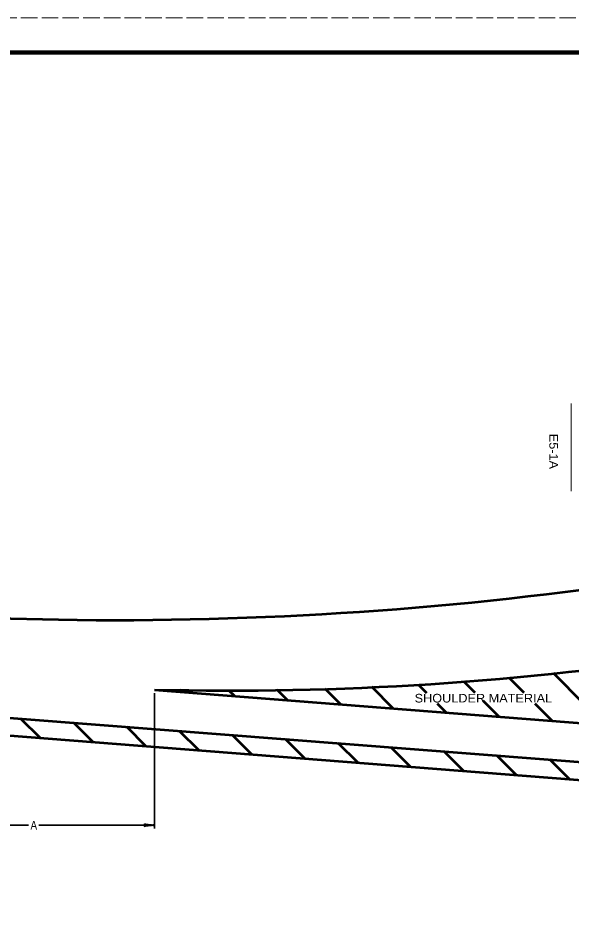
# Model space of a CAD drawing. Extents: x -281 to 399, y -258 to 182.
# Drawn here: x 24.5 to 184.7, y -78.8 to 181.6 of the extents above; entities that cross this region are included whole.
import ezdxf
from ezdxf.enums import TextEntityAlignment as Align

# ---------------------------------------------------------------- set-up
doc = ezdxf.new("R2010")
doc.units = 0
doc.header["$LTSCALE"] = 0.8
doc.linetypes.add('LONG_DASHED', pattern=[7.5, 6, -1.5])
doc.layers.add('1', color=7, linetype='Continuous', lineweight=53)
doc.layers.add('61', color=7, linetype='Continuous', lineweight=35)
doc.layers.add('2', color=7, linetype='Continuous')

msp = doc.modelspace()

# ---------------------------------------------------------------- linework, layer by layer
at = {"layer": '1', "lineweight": 13}
msp.add_line((184.743, 44.5429), (184.743, 69.8762), dxfattribs=at)
at = {"layer": '1'}
for p, q in [((-240.6297, 13.7625), (36.2368, 7.2891)), ((171.1573, -13.9157), (166.7939, -9.5523)), ((188.5777, -17.1941), (179.6273, -8.2436)), ((64.0117, -12.9926), (380.3567, -37.8742)), ((117.9044, -17.2314), (113.4621, -12.7891)), ((133.2538, -18.4387), (127.0237, -12.2087)), ((142.9353, -13.9781), (140.5067, -11.5495)), ((157.0136, -13.9142), (153.6852, -10.5857)), ((71.8562, -13.6096), (71.3122, -13.0657)), ((87.2056, -14.8168), (85.5973, -13.2087)), ((102.555, -16.0242), (99.584, -13.0532)), ((148.6033, -19.646), (146.0793, -17.1221)), ((163.9527, -20.8533), (159.3061, -16.2067)), ((179.3022, -22.0606), (174.3667, -17.1251)), ((30.984, -27.0359), (25.3669, -21.4188)), ((46.3254, -28.2353), (40.6921, -22.6018)), ((61.6668, -29.4345), (56.0172, -23.7848)), ((77.0083, -30.6338), (71.3423, -24.9679)), ((92.3498, -31.8332), (86.6675, -26.1509)), ((107.6912, -33.0325), (101.9927, -27.3339)), ((123.0327, -34.2317), (117.3178, -28.5169)), ((138.3741, -35.4311), (132.643, -29.6999)), ((153.7156, -36.6304), (147.9681, -30.883)), ((169.057, -37.8297), (163.2933, -32.066)), ((184.3984, -39.029), (178.6184, -33.249))]:
    msp.add_line(p, q, dxfattribs=at)
at = {"layer": '1', "lineweight": 35}
for p, q in [((64.0117, -13.9926), (64.0117, -53.25)), ((-5.8499, -52.25), (27.5809, -52.25)), ((30.5809, -52.25), (64.0117, -52.25))]:
    msp.add_line(p, q, dxfattribs=at)
at = {"layer": '1'}
for points in [[(-241.1311, -9.5059), (-85.5166, -12.8592), (381.7234, -48.9276)], [(383.4217, -54.5876), (-6.4749, -24.1076), (-241.3148, -19.9913)]]:
    msp.add_lwpolyline(points, dxfattribs=at)
for centre, radius, start, end in [((52.4616, 1053.2806), 1046.1173, 269.11133, 288.21006), ((85.7097, 886.1487), 899.403, 268.61761, 289.03246)]:
    msp.add_arc(centre, radius, start, end, dxfattribs=at)
at = {"layer": '1', "lineweight": 40}
for centre, major_axis, ratio, start_param, end_param in [((62.8912, -52.0384), (1.7565, -0.1757), 0.07063, 3.14071475, 5.41810995), ((62.9206, -52.5263), (1.7857, 0.1562), 0.122415, 0.89635335, 3.14159265)]:
    msp.add_ellipse(centre, major_axis=major_axis, ratio=ratio, start_param=start_param, end_param=end_param, dxfattribs=at)
at = {"layer": '61', "linetype": 'LONG_DASHED', "lineweight": 13}
msp.add_line((-280.6301, 181.553), (399.3899, 181.553), dxfattribs=at)
at = {"layer": '61', "lineweight": 158}
msp.add_lwpolyline([(388.4099, 171.553), (-250.6301, 171.553), (-250.6301, -248.467)], dxfattribs=at)

# ---------------------------------------------------------------- texts
at = {"layer": '1'}
for s, width, p in [('SHOULDER MATERIAL', 1.1, (159.3471, -16.7084)), ('A', 0.85, (29.0809, -53.5))]:
    msp.add_text(s, height=2.5, dxfattribs=dict(at, width=width)).set_placement(p, align=Align.CENTER)
at = {"layer": '2', "width": 1.1}
msp.add_text('E5-1A', height=2.5, rotation=270, dxfattribs=at).set_placement((178.4522, 56.0186), align=Align.CENTER)

doc.saveas('drawing.dxf')
